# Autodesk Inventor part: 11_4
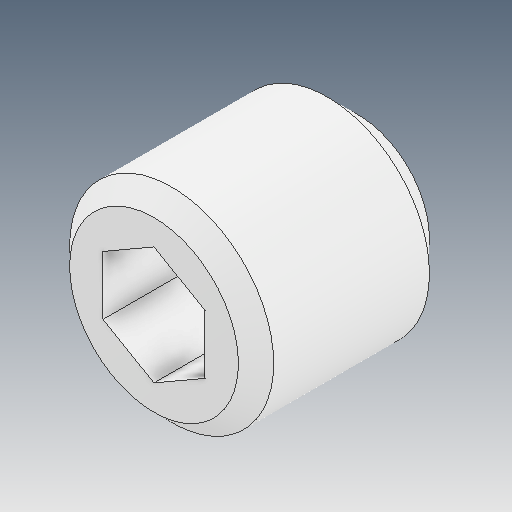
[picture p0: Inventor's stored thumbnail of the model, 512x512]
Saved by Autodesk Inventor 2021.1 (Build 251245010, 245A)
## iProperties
Created: 2021-06
Part Number: 11_4
Material: Ogólny
Document SubType Name: Modeling
Designer: user
Density: 1 g/cm^3
Appearance: Domyślna
Author: user
Revision Number: ÈÎºÎ
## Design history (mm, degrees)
feature "ÊäÈë1"
node "Bryła1"
